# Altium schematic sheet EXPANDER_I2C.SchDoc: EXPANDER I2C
size A4; Author: Silvio Navaretti; CompanyName: Arduino SRL; DrawnBy: Silvio Navaretti; Engineer: Silvio Navaretti; Organization: Arduino SRL; DocumentNumber: ASX00083; SheetNumber: 5; SheetTotal: 11; RevAuthor: Silvio Navaretti
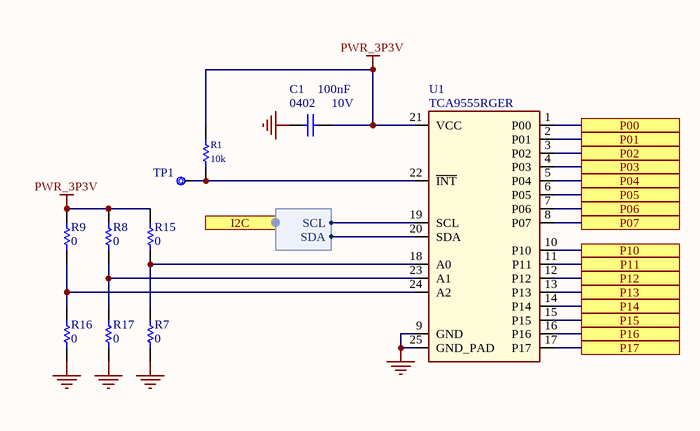
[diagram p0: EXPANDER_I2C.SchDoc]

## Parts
C1  value 100nF  Case Code (Imperial): 0402  Voltage: 10V  [CAP-0402]  (hidden comment: GRM155R61A104KA01J)
R1  value 10k  [RES-0402]  (hidden comment: CRCW040210K0FKED)
R7  value 0  [RES-0402]  (hidden comment: CRCW04020000Z0EDC)
R8  value 0  [RES-0402]  (hidden comment: CRCW04020000Z0EDC)
R9  value 0  [RES-0402]  (hidden comment: CRCW04020000Z0EDC)
R15  value 0  [RES-0402]  (hidden comment: CRCW04020000Z0EDC)
R16  value 0  [RES-0402]  (hidden comment: CRCW04020000Z0EDC)
R17  value 0  [RES-0402]  (hidden comment: CRCW04020000Z0EDC)
TP1  Test point 1.00mm  [TP-1.00MM]  (value not drawn)  (no BOM)
U1  TCA9555RGER  [PQFN50P400X400X100_HS-25N]

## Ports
I2C (harness I2C), P00, P01, P02, P03, P04, P05, P06, P07, P10, P11, P12, P13, P14, P15, P16, P17

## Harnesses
I2C: SDA, SCL

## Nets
GND: C1.1 R7.2 R16.2 R17.2 U1.9(GND) U1.25(GND_PAD)
PWR_3P3V: C1.2 R1.2 R8.1 R9.1 R15.1 U1.21(VCC)
P00: U1.1(P00) ; port P00
P01: U1.2(P01) ; port P01
P02: U1.3(P02) ; port P02
P03: U1.4(P03) ; port P03
P04: U1.5(P04) ; port P04
P05: U1.6(P05) ; port P05
P06: U1.7(P06) ; port P06
P07: U1.8(P07) ; port P07
P10: U1.10(P10) ; port P10
P11: U1.11(P11) ; port P11
P12: U1.12(P12) ; port P12
P13: U1.13(P13) ; port P13
P14: U1.14(P14) ; port P14
P15: U1.15(P15) ; port P15
P16: U1.16(P16) ; port P16
P17: U1.17(P17) ; port P17
NetR1_1: R1.1 TP1.X U1.22(~{INT})
NetR7_1: R7.1 R15.2 U1.18(A0)
NetR8_2: R8.2 R17.1 U1.23(A1)
NetR9_2: R9.2 R16.1 U1.24(A2)
NetU1_19: U1.19(SCL) ; port I2C.SCL
NetU1_20: U1.20(SDA) ; port I2C.SDA

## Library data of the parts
C1 = C0134-A.4: CAP CHIP 0402 100nF 10% 10V X5R; Manufacturer: Murata; Code Arduino: C0134
R1 = R0003-A.24: RES CHIP 0402 10k 1% 1/16W; Manufacturer: Vishay; Code Arduino: 0136; Power: 62.5mW; Temperature coefficient: 100ppm
R7-R9 R15-R17 = R0000-A.24: RES CHIP 0402 0R 1/16W; Manufacturer: Vishay; Code Arduino: 0039; Power: 62.5mW; Tolerance: 0%; Temperature coefficient: 0ppm
TP1 = UT0013-A.6: Manufacturer: This is not a component
U1 = U0167-A.6: IC 16b I2C EXPANDER with INTERRUPT; Manufacturer: Texas Instruments; Code Arduino: U0167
